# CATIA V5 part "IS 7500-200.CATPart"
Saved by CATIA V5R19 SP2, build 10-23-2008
Part number: IS 7500-200
Bounding box of the stored display mesh (mm): x -74.81 to 74.81, y -74.81 to 74.81, z 0 to 555
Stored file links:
  C:\Users\Bora\Desktop\3D Katı model\IS serisi\IS 7500\IS 7500-200.CATPart
  C:\Program Files\Dassault Systemes\B19\intel_a\reffiles\standard\MetricThickPitch.txt
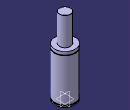
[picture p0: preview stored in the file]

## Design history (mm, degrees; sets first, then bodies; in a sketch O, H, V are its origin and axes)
Body1 (main body)
  Sketch1 on yz-plane, origin (0, 0, 0), H (0, 1, 0), V (0, 0, 1)
    point P1 (75, 330)
    point P2 (75, 325)
    point P5 (40, 554)
    point P7 (40, 554)
    point P12 (75, 325)
    point P13 (75, 330)
    arc A1 centre (75, 327.5) radius 2.5 from (75, 330) to (75, 325) ccw
    line L1 (75, 0) -> (75, 8)
    line L2 (40, 554) -> (40, 352)
    arc A2 centre (39, 554) radius 1 from (40, 554) to (39, 555) ccw
    line L3 (71, 15) -> (71, 8)
    line L4 (75, 15) -> (75, 325)
    line L5 (75, 330) -> (75, 352)
    line L6 (39, 555) -> (0, 555)
    point P15 (0, 555)
    line L7 (40, 352) -> (75, 352)
    line L8 (0, 0) -> (75, 0)
    line L9 (71, 15) -> (75, 15)
    line L10 (71, 8) -> (75, 8)
    coincidence: P15 V, P1 P13, P2 P12, P5 P7
    tangency: L6 A2
    horizontal: L7 H, L8 H, L9 H, L10 H
  Shaft1: profile Sketch1, axis Sketch1.V, angle 360
  Sketch2 on face of Shaft1 from Sketch1.L8, origin (0, 0, 0), H (1, 0, 0), V (0, -1, 0)
    point P1 (50, 0)
    distance P1 V = 50
  Hole1: placed by Sketch2, at (50, 0, 0) direction (0, 0, 1), diameter 8.376, depth 16, threaded "M10", thread diameter 10, thread depth 16, pitch 1.5
  CircPattern1: of Hole1, instances 4, angular step 90, axis from xy-plane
